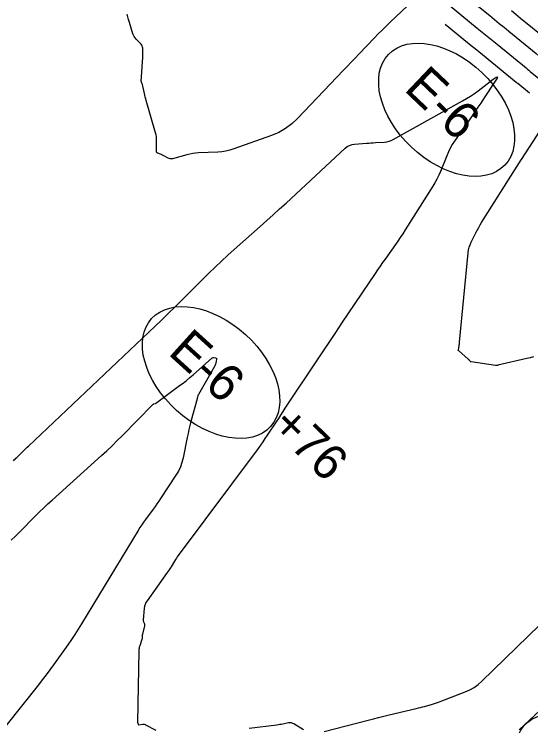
# Model space of a CAD drawing. Extents: x 1005228 to 1008882, y 1883389 to 1885754.
# Drawn here: x 1007741.8 to 1007830, y 1884530.4 to 1884651.8 of the extents above; entities that cross this region are included whole.
import ezdxf

# ---------------------------------------------------------------- set-up
doc = ezdxf.new("R2010")
doc.units = 0
for name, color, linetype in [('ATDIMS', 7, 'Continuous'), ('C-ANNO-NOTE', 7, 'Continuous'), ('R_Erosion', 7, 'Continuous'), ('S_BASELINE', 7, 'Continuous'), ('TSOBSTACLE', 7, 'Continuous')]:
    doc.layers.add(name, color=color, linetype=linetype)

msp = doc.modelspace()

# ---------------------------------------------------------------- linework, layer by layer
at = {"layer": 'ATDIMS'}
msp.add_lwpolyline([(1007826.68, 1884652.43), (1007827.46, 1884651.8), (1007828.23, 1884651.16), (1007832.6, 1884647.6)], dxfattribs=at)
at = {"layer": 'C-ANNO-NOTE'}
for points in [[(1007819.77, 1884663.48), (1007805.98, 1884650.44), (1007805.29, 1884649.78), (1007804.61, 1884649.11), (1007803.94, 1884648.44), (1007803.28, 1884647.76), (1007800.65, 1884645.01), (1007799.99, 1884644.32), (1007799.33, 1884643.64), (1007798.67, 1884642.95), (1007798.02, 1884642.26), (1007790.18, 1884634.05), (1007789.19, 1884633.12), (1007788.11, 1884632.33), (1007786.95, 1884631.66), (1007785.7, 1884631.13), (1007779.3, 1884628.84), (1007778.62, 1884628.62), (1007777.93, 1884628.46), (1007777.23, 1884628.35), (1007776.52, 1884628.29), (1007773.23, 1884628.15), (1007772.74, 1884628.11), (1007772.25, 1884628.05), (1007771.76, 1884627.96), (1007771.28, 1884627.84), (1007768.78, 1884627.17), (1007768.59, 1884627.14), (1007768.41, 1884627.15), (1007768.23, 1884627.19), (1007768.05, 1884627.27), (1007767.23, 1884627.74), (1007767.12, 1884627.8), (1007767.01, 1884627.85), (1007766.9, 1884627.9), (1007766.78, 1884627.94), (1007766.31, 1884628.09), (1007766.21, 1884628.14), (1007766.14, 1884628.21), (1007766.09, 1884628.3), (1007766.08, 1884628.41), (1007766.1, 1884630.24), (1007766.09, 1884630.58), (1007766.06, 1884630.92), (1007766, 1884631.26), (1007765.91, 1884631.59), (1007764.31, 1884637.09), (1007764.23, 1884637.39), (1007764.15, 1884637.68), (1007764.07, 1884637.98), (1007764, 1884638.28), (1007763.61, 1884640.03), (1007763.6, 1884640.05), (1007763.59, 1884640.08), (1007763.58, 1884640.11), (1007763.57, 1884640.13), (1007763.51, 1884640.23), (1007763.5, 1884640.25), (1007763.49, 1884640.28), (1007763.48, 1884640.31), (1007763.48, 1884640.34), (1007763.72, 1884644.5), (1007763.72, 1884644.69), (1007763.73, 1884644.88), (1007763.73, 1884645.07), (1007763.73, 1884645.27), (1007763.72, 1884646.04), (1007763.7, 1884646.22), (1007763.65, 1884646.4), (1007763.57, 1884646.56), (1007763.45, 1884646.7), (1007762.6, 1884647.58), (1007762.42, 1884647.78), (1007762.28, 1884648), (1007762.15, 1884648.23), (1007762.06, 1884648.48), (1007761.45, 1884650.42), (1007761.39, 1884650.59), (1007761.34, 1884650.77), (1007761.29, 1884650.94), (1007761.24, 1884651.12), (1007761.05, 1884651.83)], [(1007830.48, 1884593.37), (1007829.91, 1884593.23), (1007829.34, 1884593.09), (1007824.39, 1884591.93), (1007824.37, 1884591.92), (1007824.35, 1884591.92), (1007824.33, 1884591.91), (1007824.31, 1884591.91), (1007824.22, 1884591.89), (1007824.2, 1884591.89), (1007824.18, 1884591.88), (1007824.16, 1884591.88), (1007824.14, 1884591.88), (1007824.04, 1884591.88), (1007824.02, 1884591.88), (1007824, 1884591.88), (1007823.98, 1884591.88), (1007823.95, 1884591.88), (1007819.82, 1884592.54), (1007819.77, 1884592.55), (1007819.72, 1884592.57), (1007819.67, 1884592.6), (1007819.63, 1884592.64), (1007819.48, 1884592.82), (1007819.44, 1884592.86), (1007819.4, 1884592.9), (1007819.36, 1884592.94), (1007819.32, 1884592.98), (1007817.63, 1884594.43), (1007817.62, 1884594.43), (1007817.62, 1884594.44), (1007817.61, 1884594.45), (1007817.61, 1884594.45), (1007817.61, 1884594.49), (1007817.61, 1884594.5), (1007817.62, 1884594.51), (1007817.62, 1884594.51), (1007817.62, 1884594.52), (1007817.75, 1884595.31), (1007817.77, 1884595.44), (1007817.79, 1884595.58), (1007817.81, 1884595.71), (1007817.82, 1884595.85), (1007819.28, 1884611.14), (1007819.35, 1884611.61), (1007819.46, 1884612.06), (1007819.61, 1884612.5), (1007819.8, 1884612.93), (1007820.65, 1884614.62), (1007820.87, 1884615.04), (1007821.09, 1884615.46), (1007821.33, 1884615.87), (1007821.58, 1884616.27), (1007828.35, 1884626.98), (1007828.36, 1884626.99), (1007828.36, 1884627), (1007828.38, 1884627.03), (1007828.39, 1884627.05), (1007828.39, 1884627.05), (1007838.24, 1884642.24)], [(1007741.63, 1884575.64), (1007741.78, 1884575.78), (1007741.93, 1884575.93), (1007742.08, 1884576.08), (1007742.23, 1884576.23), (1007743.31, 1884577.27), (1007743.54, 1884577.5), (1007743.77, 1884577.72), (1007744, 1884577.94), (1007744.24, 1884578.16), (1007765.83, 1884598.6), (1007766.98, 1884599.69), (1007768.12, 1884600.8), (1007769.25, 1884601.9), (1007770.38, 1884603.02), (1007775.03, 1884607.64), (1007776.09, 1884608.68), (1007777.16, 1884609.7), (1007778.25, 1884610.71), (1007779.35, 1884611.7), (1007783.79, 1884615.63), (1007784.9, 1884616.61), (1007786, 1884617.61), (1007787.1, 1884618.6), (1007788.19, 1884619.61), (1007798.29, 1884628.95), (1007798.65, 1884629.23), (1007799.04, 1884629.44), (1007799.46, 1884629.58), (1007799.91, 1884629.65), (1007801.92, 1884629.8), (1007802.31, 1884629.83), (1007802.7, 1884629.86), (1007803.09, 1884629.89), (1007803.48, 1884629.91), (1007805.03, 1884630.01), (1007805.42, 1884630.06), (1007805.79, 1884630.15), (1007806.15, 1884630.27), (1007806.49, 1884630.44), (1007818.34, 1884637.02), (1007819.03, 1884637.42), (1007819.71, 1884637.85), (1007820.37, 1884638.3), (1007821.01, 1884638.77), (1007823.55, 1884640.72), (1007824.05, 1884641.07), (1007824.28, 1884641.12), (1007824.24, 1884640.89), (1007823.93, 1884640.37), (1007821.92, 1884637.37), (1007821.44, 1884636.65), (1007820.95, 1884635.94), (1007820.46, 1884635.22), (1007819.97, 1884634.5), (1007816.98, 1884630.18), (1007816.59, 1884629.58), (1007816.24, 1884628.96), (1007815.92, 1884628.33), (1007815.63, 1884627.67), (1007814.57, 1884625), (1007814.29, 1884624.34), (1007813.97, 1884623.7), (1007813.63, 1884623.07), (1007813.26, 1884622.46), (1007808.53, 1884615.01), (1007808.13, 1884614.38), (1007807.71, 1884613.75), (1007807.29, 1884613.13), (1007806.86, 1884612.51), (1007805.12, 1884610.05), (1007804.68, 1884609.44), (1007804.25, 1884608.82), (1007803.83, 1884608.2), (1007803.4, 1884607.57), (1007797.69, 1884599.11), (1007796.64, 1884597.55), (1007795.59, 1884595.98), (1007794.55, 1884594.42), (1007793.5, 1884592.85), (1007788.01, 1884584.6), (1007787.63, 1884584.03), (1007787.25, 1884583.45), (1007786.88, 1884582.88), (1007786.5, 1884582.31), (1007784.99, 1884580.01), (1007784.6, 1884579.44), (1007784.21, 1884578.87), (1007783.82, 1884578.31), (1007783.41, 1884577.76), (1007769.8, 1884559.51), (1007769.63, 1884559.27), (1007769.47, 1884559.04), (1007769.31, 1884558.79), (1007769.15, 1884558.55), (1007768.55, 1884557.56), (1007768.4, 1884557.31), (1007768.24, 1884557.07), (1007768.08, 1884556.83), (1007767.91, 1884556.59), (1007764.46, 1884551.77), (1007764.27, 1884551.47), (1007764.13, 1884551.15), (1007764.04, 1884550.82), (1007763.98, 1884550.47), (1007763.82, 1884548.5), (1007763.81, 1884548.41), (1007763.82, 1884548.33), (1007763.84, 1884548.25), (1007763.87, 1884548.16), (1007764.01, 1884547.84), (1007764.04, 1884547.76), (1007764.05, 1884547.68), (1007764.05, 1884547.6), (1007764.04, 1884547.52), (1007763.68, 1884546.1), (1007763.66, 1884546.03), (1007763.65, 1884545.95), (1007763.64, 1884545.87), (1007763.64, 1884545.8), (1007763.63, 1884545.48), (1007763.62, 1884545.4), (1007763.61, 1884545.33), (1007763.6, 1884545.25), (1007763.57, 1884545.18), (1007763.21, 1884544.07), (1007763.14, 1884543.86), (1007763.1, 1884543.65), (1007763.07, 1884543.43), (1007763.06, 1884543.21), (1007762.84, 1884531.08), (1007762.84, 1884531.05), (1007762.84, 1884531.01), (1007762.85, 1884530.98), (1007762.86, 1884530.95), (1007762.9, 1884530.8), (1007762.91, 1884530.79), (1007762.92, 1884530.77), (1007762.92, 1884530.75), (1007762.93, 1884530.73), (1007762.97, 1884530.66), (1007762.98, 1884530.65), (1007762.99, 1884530.64), (1007763, 1884530.64), (1007763.02, 1884530.63), (1007763.74, 1884530.72), (1007763.87, 1884530.72), (1007763.99, 1884530.71), (1007764.11, 1884530.68), (1007764.22, 1884530.63), (1007765.98, 1884529.69)], [(1007741.26, 1884562.13), (1007741.97, 1884562.8), (1007742.66, 1884563.48), (1007745.41, 1884566.25), (1007746.11, 1884566.93), (1007746.81, 1884567.61), (1007747.52, 1884568.28), (1007748.24, 1884568.93), (1007756.67, 1884576.53), (1007757.59, 1884577.37), (1007758.49, 1884578.22), (1007759.38, 1884579.09), (1007760.26, 1884579.97), (1007765.37, 1884585.21), (1007765.42, 1884585.25), (1007765.48, 1884585.29), (1007765.54, 1884585.33), (1007765.61, 1884585.35), (1007765.88, 1884585.43), (1007765.95, 1884585.45), (1007766.01, 1884585.48), (1007766.07, 1884585.52), (1007766.13, 1884585.56), (1007770.02, 1884588.46), (1007770.61, 1884588.9), (1007771.19, 1884589.36), (1007771.76, 1884589.84), (1007772.32, 1884590.32), (1007775.52, 1884593.15), (1007775.58, 1884593.2), (1007775.66, 1884593.23), (1007775.74, 1884593.24), (1007775.82, 1884593.24), (1007776.17, 1884593.2), (1007776.25, 1884593.17), (1007776.3, 1884593.13), (1007776.32, 1884593.08), (1007776.32, 1884593), (1007776.19, 1884592.28), (1007776.15, 1884592.13), (1007776.11, 1884591.99), (1007776.05, 1884591.85), (1007775.98, 1884591.71), (1007773.22, 1884586.95), (1007773.19, 1884586.89), (1007773.17, 1884586.84), (1007773.15, 1884586.78), (1007773.13, 1884586.72), (1007773.06, 1884586.48), (1007773.05, 1884586.42), (1007773.03, 1884586.36), (1007773.02, 1884586.3), (1007773, 1884586.24), (1007771.95, 1884582.33), (1007771.78, 1884581.66), (1007771.61, 1884580.98), (1007771.46, 1884580.3), (1007771.32, 1884579.62), (1007770.62, 1884576.16), (1007770.42, 1884575.37), (1007770.15, 1884574.61), (1007769.81, 1884573.88), (1007769.4, 1884573.18), (1007766.77, 1884569.19), (1007766.47, 1884568.73), (1007766.15, 1884568.28), (1007765.83, 1884567.83), (1007765.51, 1884567.38), (1007764.19, 1884565.61), (1007763.86, 1884565.17), (1007763.55, 1884564.71), (1007763.24, 1884564.25), (1007762.95, 1884563.78), (1007753.26, 1884547.82), (1007752.7, 1884546.92), (1007752.13, 1884546.03), (1007751.54, 1884545.15), (1007750.93, 1884544.28), (1007748.46, 1884540.84), (1007747.84, 1884539.98), (1007747.21, 1884539.13), (1007746.57, 1884538.28), (1007745.91, 1884537.45), (1007740.37, 1884530.42)], [(1007794.7, 1884529.46), (1007802.24, 1884531.4), (1007803.13, 1884531.63), (1007804.01, 1884531.85), (1007804.9, 1884532.07), (1007805.79, 1884532.29), (1007810.44, 1884533.39), (1007810.79, 1884533.48), (1007811.13, 1884533.57), (1007811.48, 1884533.66), (1007811.82, 1884533.76), (1007813.19, 1884534.16), (1007813.53, 1884534.26), (1007813.87, 1884534.37), (1007814.21, 1884534.49), (1007814.54, 1884534.61), (1007818.77, 1884536.21), (1007819.56, 1884536.56), (1007820.3, 1884536.98), (1007821, 1884537.48), (1007821.65, 1884538.05), (1007843.37, 1884559.15)], [(1007828.03, 1884529.77), (1007845.59, 1884546.16)], [(1007781.9, 1884530.04), (1007786.63, 1884530.63), (1007786.88, 1884530.66), (1007787.13, 1884530.7), (1007787.38, 1884530.74), (1007787.62, 1884530.79), (1007788.61, 1884530.98), (1007788.85, 1884531.01), (1007789.09, 1884530.99), (1007789.31, 1884530.92), (1007789.53, 1884530.81), (1007791.18, 1884529.8)]]:
    msp.add_lwpolyline(points, dxfattribs=at)
at = {"layer": 'R_Erosion'}
for centre, major_axis in [((1007815.62, 1884635.51), (9.93, -9.44)), ((1007775.39, 1884590.7), (10.15, -9.2)), ((1007839.1, 1884521.38), (10.28, -9.05))]:
    msp.add_ellipse(centre, major_axis=major_axis, ratio=0.638788, dxfattribs=at)
at = {"layer": 'TSOBSTACLE'}
for points in [[(1007818.07, 1884655.59), (1007822.99, 1884651.58), (1007823.8, 1884650.92), (1007824.61, 1884650.25), (1007825.42, 1884649.59), (1007826.23, 1884648.93), (1007830.89, 1884645.13), (1007830.99, 1884645.05), (1007831.09, 1884644.97), (1007831.19, 1884644.89), (1007831.29, 1884644.81), (1007831.68, 1884644.49), (1007831.78, 1884644.41), (1007831.88, 1884644.33), (1007831.98, 1884644.25), (1007832.07, 1884644.16), (1007838.93, 1884638.57), (1007838.97, 1884638.54), (1007839.02, 1884638.5), (1007839.11, 1884638.43), (1007839.15, 1884638.39), (1007839.2, 1884638.35), (1007845.66, 1884633.07)], [(1007815.62, 1884653.73), (1007820.85, 1884649.46), (1007821.7, 1884648.77), (1007822.54, 1884648.08), (1007823.39, 1884647.39), (1007824.24, 1884646.7), (1007829.19, 1884642.66), (1007829.25, 1884642.61), (1007829.31, 1884642.56), (1007829.37, 1884642.51), (1007829.43, 1884642.46), (1007829.67, 1884642.27), (1007829.73, 1884642.22), (1007829.79, 1884642.17), (1007829.85, 1884642.12), (1007829.91, 1884642.07), (1007835.4, 1884637.6)], [(1007829.75, 1884638.34), (1007827.75, 1884639.98), (1007827.71, 1884640.01), (1007827.66, 1884640.05), (1007827.58, 1884640.12), (1007827.53, 1884640.16), (1007827.49, 1884640.19), (1007821.75, 1884644.87), (1007821.11, 1884645.39), (1007820.47, 1884645.91), (1007819.83, 1884646.43), (1007819.19, 1884646.95), (1007815.36, 1884650.08)]]:
    msp.add_lwpolyline(points, dxfattribs=at)

# ---------------------------------------------------------------- texts
at = {"layer": 'R_Erosion'}
for rotation, p in [(316.4595, (1007808.16, 1884638.92)), (317.8286, (1007767.86, 1884593.93))]:
    msp.add_text('E-6', height=6.25, rotation=rotation, dxfattribs=at).set_placement(p)
at = {"layer": 'S_BASELINE'}
msp.add_text('+76', height=6, rotation=315.6546, dxfattribs=at).set_placement((1007785.37, 1884581.33))

doc.saveas('drawing.dxf')
